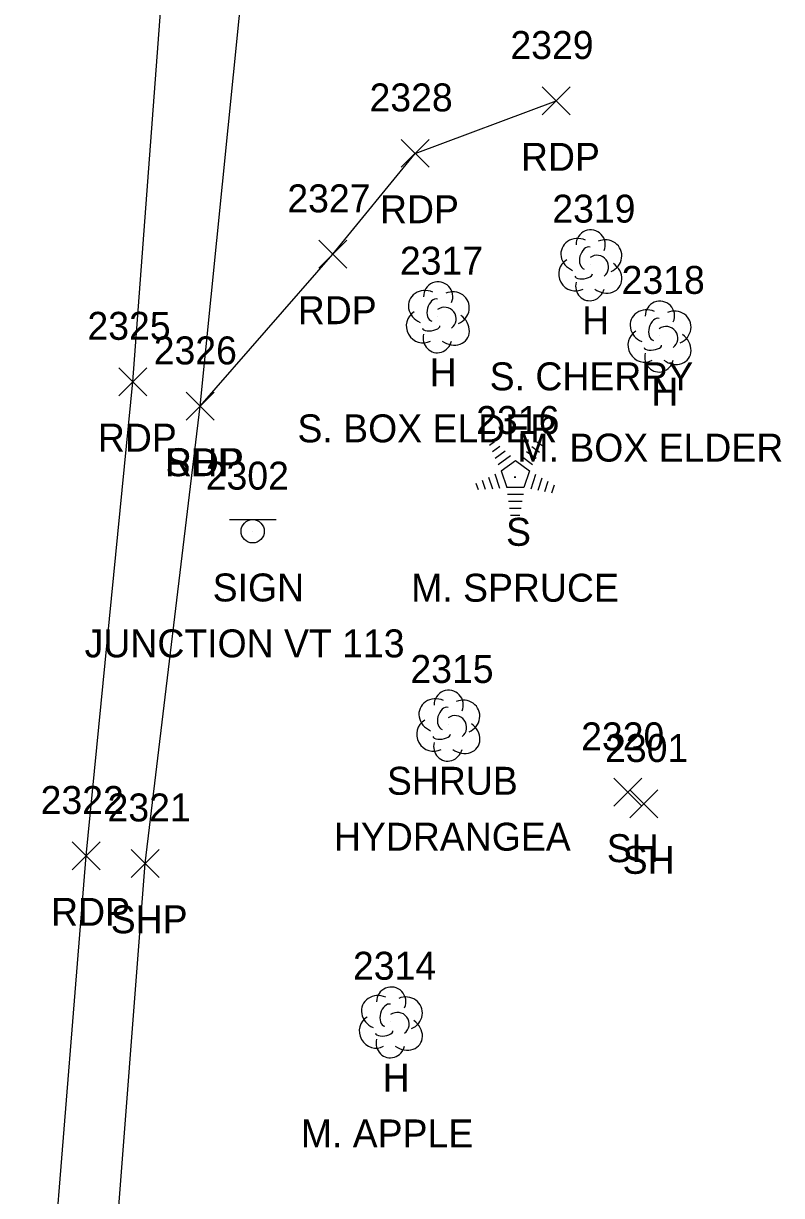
# Model space of a CAD drawing. Extents: x 1653908 to 1654393, y 539913 to 544256.
# Drawn here: x 1654121 to 1654175.3, y 542096.3 to 542180.1 of the extents above; entities that cross this region are included whole.
import ezdxf

# ---------------------------------------------------------------- set-up
doc = ezdxf.new("R2010")
doc.units = 0
for name, color, linetype in [('L_A', 7, 'Continuous'), ('L_C', 7, 'Continuous'), ('L_I', 7, 'Continuous'), ('L_TIC', 7, 'Continuous'), ('LSH', 7, 'Continuous'), ('LTC', 7, 'Continuous'), ('LTD', 7, 'Continuous'), ('P_A', 7, 'Continuous'), ('P_I', 7, 'Continuous'), ('P_TIC', 7, 'Continuous'), ('PET', 7, 'Continuous'), ('PSP', 7, 'Continuous'), ('S_A', 7, 'Continuous'), ('S_C', 7, 'Continuous'), ('S_I', 7, 'Continuous'), ('SSGN', 7, 'Continuous')]:
    doc.layers.add(name, color=color, linetype=linetype)

msp = doc.modelspace()

# ---------------------------------------------------------------- linework, layer by layer
at = {"layer": 'L_TIC'}
for points in [[(1654163.268, 542124.122), (1654165.268, 542126.122)], [(1654165.268, 542124.122), (1654163.268, 542126.122)], [(1654164.405, 542123.287), (1654166.405, 542125.287)], [(1654166.405, 542123.287), (1654164.405, 542125.287)]]:
    msp.add_lwpolyline(points, dxfattribs=at)
at = {"layer": 'LSH'}
msp.add_line((1654151.4, 542129.943), (1654151.4, 542129.943), dxfattribs=at)
msp.add_line((1654151.4, 542129.943), (1654151.4, 542129.943), dxfattribs=at)
msp.add_arc((1654151.446, 542131.377), 1.047, 335.52715, 180.95627, dxfattribs=at)
for centre, major_axis, ratio, start_param, end_param in [((1654150.608, 542130.61), (1.21, -0.512), 0.895232, 1.570796, 4.712389), ((1654152.441, 542130.527), (-1.141, -0.483), 0.949671, 1.570796, 4.712389), ((1654151.191, 542130.402), (-0.208, -0.792), 0.645439, 3.141593, 6.283185), ((1654151.9, 542129.777), (-0.5, 0.667), 0.989748, 3.141593, 6.283185), ((1654150.316, 542129.235), (0.584, -1.042), 0.959034, 3.141593, 6.283185), ((1654152.4, 542129.11), (-1.09, 0.792), 0.841452, 1.570796, 4.712389), ((1654150.941, 542129.193), (-0.625, -0.083), 0.423636, 0, 3.141593), ((1654151.4, 542128.443), (0.265, 1.061), 0.942809, 1.570796, 4.712389)]:
    msp.add_ellipse(centre, major_axis=major_axis, ratio=ratio, start_param=start_param, end_param=end_param, dxfattribs=at)
at = {"layer": 'LTC'}
for p, q in [((1654154.358, 542149.965), (1654154.713, 542150.222)), ((1654157.756, 542150.205), (1654158.176, 542149.9)), ((1654154.568, 542149.499), (1654155.097, 542149.883)), ((1654154.777, 542149.033), (1654155.481, 542149.545)), ((1654154.987, 542148.568), (1654155.865, 542149.205)), ((1654156.643, 542149.16), (1654157.453, 542148.571)), ((1654157.014, 542149.508), (1654157.694, 542149.015)), ((1654157.385, 542149.857), (1654157.935, 542149.458)), ((1654155.211, 542148.113), (1654156.223, 542148.847)), ((1654156.223, 542148.847), (1654157.22, 542148.122)), ((1654153.846, 542147.46), (1654154.058, 542146.809)), ((1654154.301, 542147.677), (1654154.573, 542146.842)), ((1654154.757, 542147.893), (1654155.088, 542146.874)), ((1654155.211, 542148.113), (1654155.599, 542146.919)), ((1654157.22, 542148.122), (1654156.829, 542146.919)), ((1654157.658, 542147.851), (1654157.32, 542146.812)), ((1654158.102, 542147.601), (1654157.815, 542146.716)), ((1654153.391, 542147.244), (1654153.543, 542146.776)), ((1654156.829, 542146.919), (1654155.599, 542146.919)), ((1654158.547, 542147.351), (1654158.31, 542146.621)), ((1654158.991, 542147.1), (1654158.804, 542146.526)), ((1654156.791, 542146.419), (1654155.646, 542146.419)), ((1654156.707, 542145.919), (1654155.719, 542145.919)), ((1654156.623, 542145.419), (1654155.791, 542145.419)), ((1654156.539, 542144.919), (1654155.864, 542144.919))]:
    msp.add_line(p, q, dxfattribs=at)
at = {"layer": 'LTD'}
for p, q in [((1654161.558, 542162.879), (1654161.558, 542162.879)), ((1654161.558, 542162.879), (1654161.558, 542162.879)), ((1654150.649, 542159.158), (1654150.649, 542159.158)), ((1654150.649, 542159.158), (1654150.649, 542159.158)), ((1654166.51, 542157.78), (1654166.51, 542157.78)), ((1654166.51, 542157.78), (1654166.51, 542157.78)), ((1654147.289, 542108.71), (1654147.289, 542108.71)), ((1654147.289, 542108.71), (1654147.289, 542108.71))]:
    msp.add_line(p, q, dxfattribs=at)
for centre in [(1654161.605, 542164.312), (1654150.696, 542160.592), (1654166.557, 542159.214), (1654147.336, 542110.144)]:
    msp.add_arc(centre, 1.047, 335.52715, 180.95627, dxfattribs=at)
for centre, major_axis, ratio, start_param, end_param in [((1654160.766, 542163.545), (1.21, -0.512), 0.895232, 1.570796, 4.712389), ((1654162.6, 542163.462), (-1.141, -0.483), 0.949671, 1.570796, 4.712389), ((1654161.35, 542163.337), (-0.208, -0.792), 0.645439, 3.141593, 6.283185), ((1654162.058, 542162.712), (-0.5, 0.667), 0.989748, 3.141593, 6.283185), ((1654160.475, 542162.17), (0.584, -1.042), 0.959034, 3.141593, 6.283185), ((1654162.558, 542162.045), (-1.09, 0.792), 0.841452, 1.570796, 4.712389), ((1654161.1, 542162.128), (-0.625, -0.083), 0.423636, 0, 3.141593), ((1654149.858, 542159.825), (1.21, -0.512), 0.895232, 1.570796, 4.712389), ((1654151.691, 542159.742), (-1.141, -0.483), 0.949671, 1.570796, 4.712389), ((1654161.558, 542161.379), (0.265, 1.061), 0.942809, 1.570796, 4.712389), ((1654150.441, 542159.617), (-0.208, -0.792), 0.645439, 3.141593, 6.283185), ((1654149.566, 542158.45), (0.584, -1.042), 0.959034, 3.141593, 6.283185), ((1654151.15, 542158.992), (-0.5, 0.667), 0.989748, 3.141593, 6.283185), ((1654151.65, 542158.325), (-1.09, 0.792), 0.841452, 1.570796, 4.712389), ((1654165.718, 542158.446), (1.21, -0.512), 0.895232, 1.570796, 4.712389), ((1654167.551, 542158.363), (-1.141, -0.483), 0.949671, 1.570796, 4.712389), ((1654150.191, 542158.408), (-0.625, -0.083), 0.423636, 0, 3.141593), ((1654166.301, 542158.238), (-0.208, -0.792), 0.645439, 3.141593, 6.283185), ((1654167.01, 542157.613), (-0.5, 0.667), 0.989748, 3.141593, 6.283185), ((1654150.65, 542157.658), (0.265, 1.061), 0.942809, 1.570796, 4.712389), ((1654165.427, 542157.071), (0.584, -1.042), 0.959034, 3.141593, 6.283185), ((1654167.51, 542156.947), (-1.09, 0.792), 0.841452, 1.570796, 4.712389), ((1654166.052, 542157.03), (-0.625, -0.083), 0.423636, 0, 3.141593), ((1654166.51, 542156.28), (0.265, 1.061), 0.942809, 1.570796, 4.712389), ((1654146.498, 542109.376), (1.21, -0.512), 0.895232, 1.570796, 4.712389), ((1654148.331, 542109.293), (-1.141, -0.483), 0.949671, 1.570796, 4.712389), ((1654147.081, 542109.168), (-0.208, -0.792), 0.645439, 3.141593, 6.283185), ((1654146.206, 542108.001), (0.584, -1.042), 0.959034, 3.141593, 6.283185), ((1654147.789, 542108.543), (-0.5, 0.667), 0.989748, 3.141593, 6.283185), ((1654146.831, 542107.96), (-0.625, -0.083), 0.423636, 0, 3.141593), ((1654148.29, 542107.877), (-1.09, 0.792), 0.841452, 1.570796, 4.712389), ((1654147.29, 542107.21), (0.265, 1.061), 0.942809, 1.570796, 4.712389)]:
    msp.add_ellipse(centre, major_axis=major_axis, ratio=ratio, start_param=start_param, end_param=end_param, dxfattribs=at)
at = {"layer": 'P_TIC'}
for points in [[(1654158.128, 542173.586), (1654160.128, 542175.586)], [(1654160.128, 542173.586), (1654158.128, 542175.586)], [(1654148.043, 542169.835), (1654150.043, 542171.835)], [(1654150.043, 542169.835), (1654148.043, 542171.835)], [(1654142.16, 542162.613), (1654144.16, 542164.613)], [(1654144.16, 542162.613), (1654142.16, 542164.613)], [(1654127.858, 542153.493), (1654129.858, 542155.493)], [(1654129.858, 542153.493), (1654127.858, 542155.493)], [(1654132.658, 542151.736), (1654134.658, 542153.736)], [(1654134.658, 542151.736), (1654132.658, 542153.736)], [(1654132.658, 542151.736), (1654134.658, 542153.736)], [(1654134.658, 542151.736), (1654132.658, 542153.736)], [(1654124.512, 542119.567), (1654126.512, 542121.567)], [(1654126.512, 542119.567), (1654124.512, 542121.567)], [(1654128.731, 542119.034), (1654130.731, 542121.034)], [(1654130.731, 542119.034), (1654128.731, 542121.034)]]:
    msp.add_lwpolyline(points, dxfattribs=at)
at = {"layer": 'PET'}
for points in [[(1654079.776, 541659.551), (1654080.091, 541663.585), (1654084.434, 541705.035), (1654088.467, 541726.588), (1654090.823, 541750.421), (1654095.245, 541793.922), (1654098.735, 541834.906), (1654102.668, 541873.549), (1654106.19, 541915.359), (1654108.801, 541937.78), (1654112.78, 541976.541), (1654113.712, 541994.764), (1654118.507, 542040.261), (1654122.37, 542081.456), (1654125.512, 542120.567), (1654128.858, 542154.493), (1654132.07, 542197.521), (1654136.387, 542232.744)], [(1654133.658, 542152.736), (1654143.16, 542163.613), (1654149.043, 542170.835), (1654159.128, 542174.586)]]:
    msp.add_lwpolyline(points, dxfattribs=at)
at = {"layer": 'PSP'}
msp.add_lwpolyline([(1654094.458, 541721.214), (1654096.104, 541749.586), (1654101.261, 541800.15), (1654104.956, 541834.324), (1654108.508, 541872.884), (1654110.153, 541890.734), (1654111.767, 541915.009), (1654113.741, 541937.092), (1654116.462, 541969.541), (1654117.65, 541994.217), (1654121.735, 542040.282), (1654126.757, 542081.182), (1654129.731, 542120.034), (1654133.658, 542152.736), (1654138.064, 542196.396), (1654141.276, 542231.97)], dxfattribs=at)
at = {"layer": 'SSGN'}
for p, q in [((1654135.774, 542144.627), (1654139.107, 542144.627)), ((1654137.421, 542143.794), (1654137.421, 542143.794))]:
    msp.add_line(p, q, dxfattribs=at)
msp.add_circle((1654137.421, 542143.794), 0.833, dxfattribs=at)

# ---------------------------------------------------------------- texts
at = {"layer": 'L_A'}
for s, p in [('H', (1654160.991, 542157.879)), ('H', (1654150.083, 542154.158)), ('H', (1654165.943, 542152.78)), ('S', (1654155.549, 542142.756)), ('SHRUB', (1654147.029, 542124.943)), ('SH', (1654162.756, 542120.122)), ('SH', (1654163.893, 542119.287)), ('H', (1654146.722, 542103.71))]:
    msp.add_text(s, height=2, dxfattribs=at).set_placement(p)
at = {"layer": 'L_C'}
for s, p in [('S. CHERRY', (1654154.377, 542153.879)), ('S. BOX ELDER', (1654140.626, 542150.158)), ('M. BOX ELDER', (1654156.36, 542148.78)), ('M. SPRUCE', (1654148.761, 542138.756)), ('HYDRANGEA', (1654143.234, 542120.943)), ('M. APPLE', (1654140.864, 542099.71))]:
    msp.add_text(s, height=2, dxfattribs=at).set_placement(p)
at = {"layer": 'L_I'}
for s, p in [('2319', (1654158.858, 542165.879)), ('2317', (1654147.957, 542162.158)), ('2318', (1654163.817, 542160.78)), ('2316', (1654153.415, 542150.756)), ('2315', (1654148.707, 542132.943)), ('2320', (1654160.921, 542128.122)), ('2301', (1654162.634, 542127.287)), ('2314', (1654144.597, 542111.71))]:
    msp.add_text(s, height=2, dxfattribs=at).set_placement(p)
at = {"layer": 'LTC'}
msp.add_text('.', height=1.037, rotation=270, dxfattribs=at).set_placement((1654156.106, 542147.86))
at = {"layer": 'P_A'}
for s, p in [('RDP', (1654156.616, 542169.586)), ('RDP', (1654146.531, 542165.835)), ('RDP', (1654140.648, 542158.613)), ('RDP', (1654126.347, 542149.493)), ('SHP', (1654131.193, 542147.736)), ('RDP', (1654131.146, 542147.736)), ('RDP', (1654123, 542115.567)), ('SHP', (1654127.266, 542115.034))]:
    msp.add_text(s, height=2, dxfattribs=at).set_placement(p)
at = {"layer": 'P_I'}
for s, p in [('2329', (1654155.86, 542177.586)), ('2328', (1654145.783, 542173.835)), ('2327', (1654139.901, 542166.613)), ('2325', (1654125.599, 542157.493)), ('2326', (1654130.343, 542155.736)), ('2326', (1654130.343, 542155.736)), ('2322', (1654122.252, 542123.567)), ('2321', (1654127.038, 542123.034))]:
    msp.add_text(s, height=2, dxfattribs=at).set_placement(p)
at = {"layer": 'S_A'}
msp.add_text('SIGN', height=2, dxfattribs=at).set_placement((1654134.559, 542138.774))
at = {"layer": 'S_C'}
msp.add_text('JUNCTION VT 113', height=2, dxfattribs=at).set_placement((1654125.402, 542134.774))
at = {"layer": 'S_I'}
msp.add_text('2302', height=2, dxfattribs=at).set_placement((1654134.063, 542146.774))

doc.saveas('drawing.dxf')
